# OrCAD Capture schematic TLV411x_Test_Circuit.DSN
size A; title: TLV4110, TLV4111, TLV4112, TLV4113 FAMILY OF HIGH OUTPUT; rev: 1.2; note: Datasheet: SLOS289E   EVM: N/A
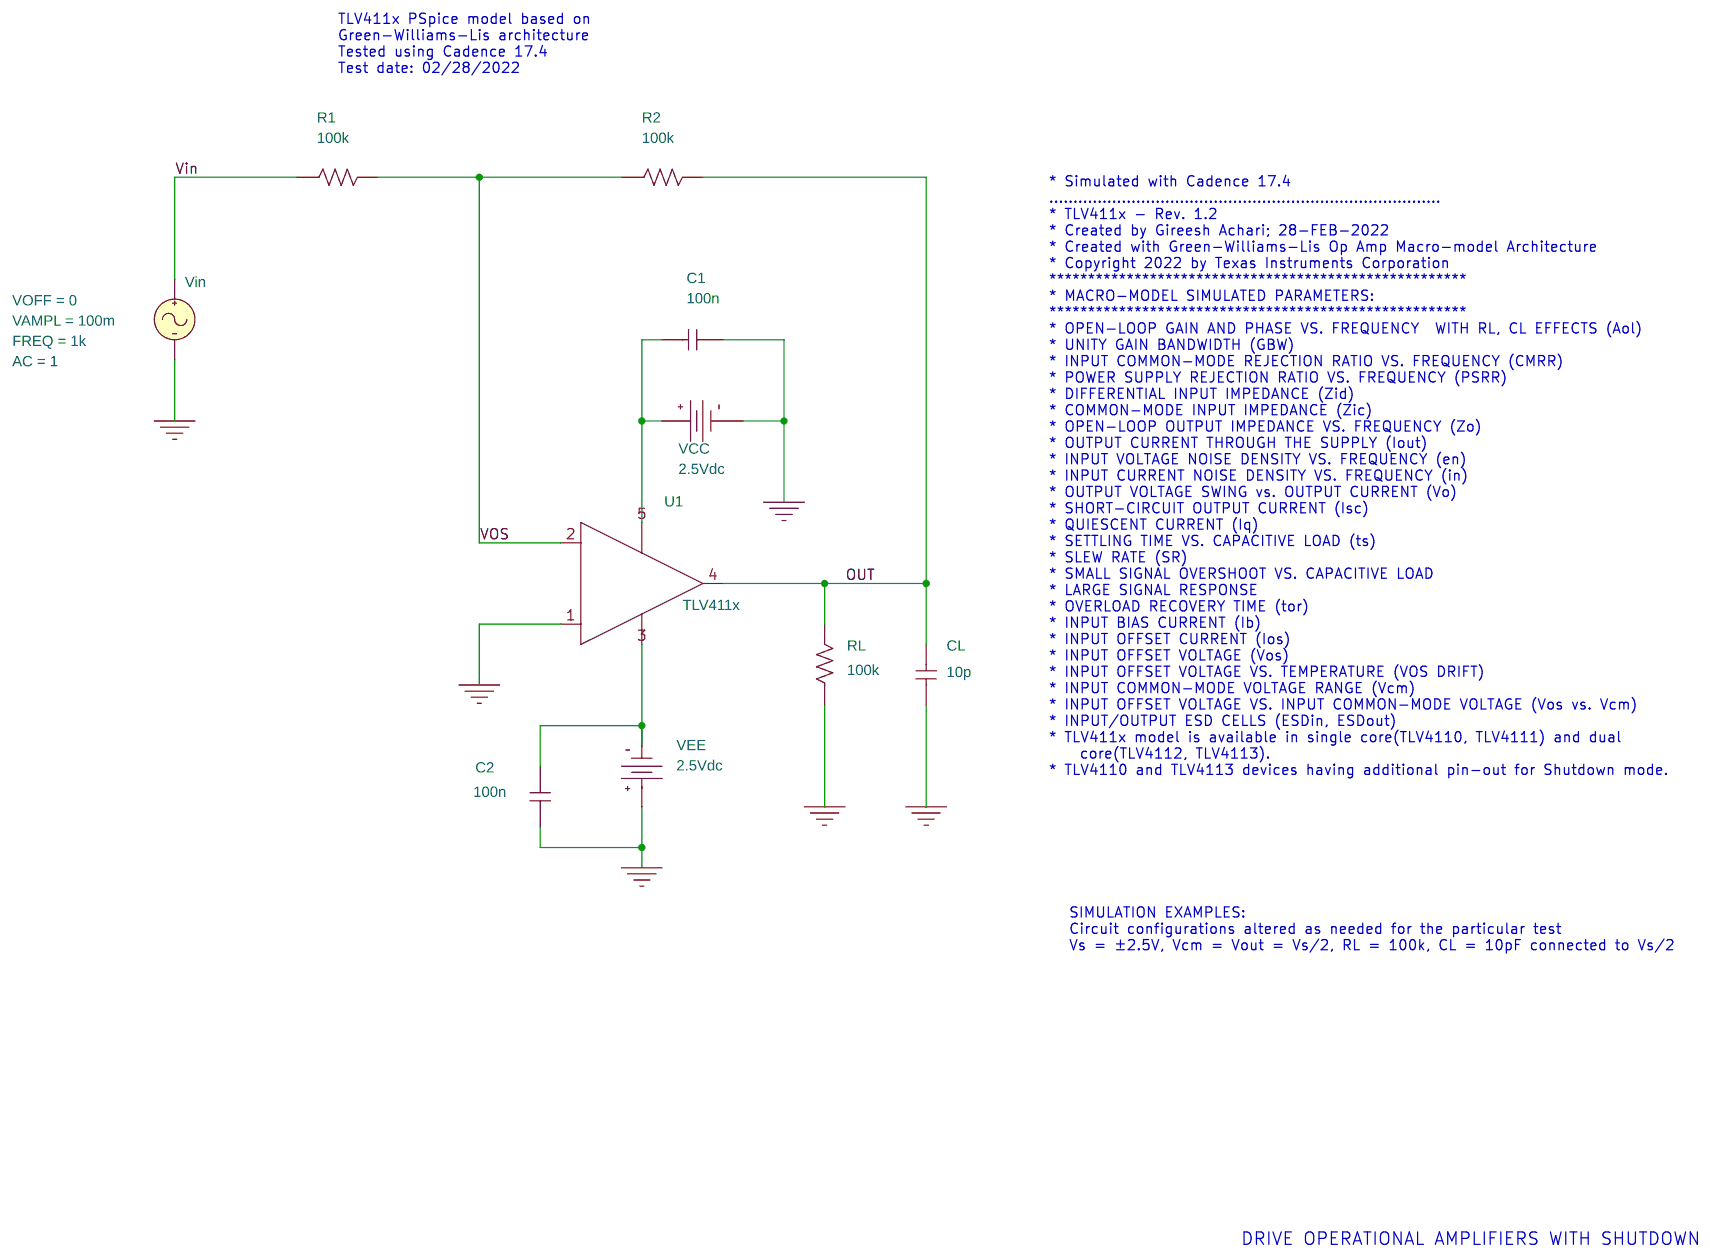
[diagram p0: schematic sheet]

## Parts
C1  100n  [cap196]
C2  100n  [cap196]
CL  10p  [cap196]
R1  100k  [AXRC05]
R2  100k  [AXRC05]
RL  100k  [AXRC05]
U1  TLV411x
VCC  VDC
VEE  VDC
Vin  VSIN

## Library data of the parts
C1 C2 CL = C
R1 R2 RL = R
U1 = TLV411x
VCC VEE = VDC: DC: 2.5Vdc
Vin = VSIN: AC: 1; FREQ: 1k; VAMPL: 100m; VOFF: 0

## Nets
Vin: R1.1 Vin.1(+)
0: C1.2 C2.1 CL.2 RL.1 U1.1(+) VCC.1(-) VEE.0(+) Vin.2(-)
OUT: CL.1 R2.2 RL.2 U1.4(OUT)
VOS: R1.2 R2.1 U1.2(-)
N27303: C1.1 U1.5(V+) VCC.0(+)
N27354: C2.2 U1.3(V-) VEE.1(-)

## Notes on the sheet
- TLV411x PSpice model based on
  Green-Williams-Lis architecture
  Tested using Cadence 17.4
  Test date: 02/28/2022
- * Simulated with Cadence 17.4
  .................................................................................
  * TLV411x - Rev. 1.2
  * Created by Gireesh Achari; 28-FEB-2022
  * Created with Green-Williams-Lis Op Amp Macro-model Architecture
  * Copyright 2022 by Texas Instruments Corporation
  ******************************************************
  * MACRO-MODEL SIMULATED PARAMETERS:
  ******************************************************
  * OPEN-LOOP GAIN AND PHASE VS. FREQUENCY  WITH RL, CL EFFECTS (Aol)
  * UNITY GAIN BANDWIDTH (GBW)
  * INPUT COMMON-MODE REJECTION RATIO VS. FREQUENCY (CMRR)
  * POWER SUPPLY REJECTION RATIO VS. FREQUENCY (PSRR)
  * DIFFERENTIAL INPUT IMPEDANCE (Zid)
  * COMMON-MODE INPUT IMPEDANCE (Zic)
  * OPEN-LOOP OUTPUT IMPEDANCE VS. FREQUENCY (Zo)
  * OUTPUT CURRENT THROUGH THE SUPPLY (Iout)
  * INPUT VOLTAGE NOISE DENSITY VS. FREQUENCY (en)
  * INPUT CURRENT NOISE DENSITY VS. FREQUENCY (in)
  * OUTPUT VOLTAGE SWING vs. OUTPUT CURRENT (Vo)
  * SHORT-CIRCUIT OUTPUT CURRENT (Isc)
  * QUIESCENT CURRENT (Iq)
  * SETTLING TIME VS. CAPACITIVE LOAD (ts)
  * SLEW RATE (SR)
  * SMALL SIGNAL OVERSHOOT VS. CAPACITIVE LOAD
  * LARGE SIGNAL RESPONSE
  * OVERLOAD RECOVERY TIME (tor)
  * INPUT BIAS CURRENT (Ib)
  * INPUT OFFSET CURRENT (Ios)
  * INPUT OFFSET VOLTAGE (Vos)
  * INPUT OFFSET VOLTAGE VS. TEMPERATURE (VOS DRIFT)
  * INPUT COMMON-MODE VOLTAGE RANGE (Vcm)
  * INPUT OFFSET VOLTAGE VS. INPUT COMMON-MODE VOLTAGE (Vos vs. Vcm)
  * INPUT/OUTPUT ESD CELLS (ESDin, ESDout)
  * TLV411x model is available in single core(TLV4110, TLV4111) and dual
      core(TLV4112, TLV4113).
  * TLV4110 and TLV4113 devices having additional pin-out for Shutdown mode.
- SIMULATION EXAMPLES:
  Circuit configurations altered as needed for the particular test
  Vs = ±2.5V, Vcm = Vout = Vs/2, RL = 100k, CL = 10pF connected to Vs/2
- DRIVE OPERATIONAL AMPLIFIERS WITH SHUTDOWN
